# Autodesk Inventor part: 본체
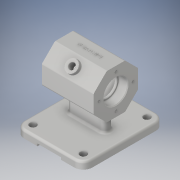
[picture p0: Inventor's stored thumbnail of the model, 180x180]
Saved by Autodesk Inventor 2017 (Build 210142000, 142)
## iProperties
Part Number: 본체
Material: 알루미늄 6061
Document SubType Name: Modeling
Designer: Administrator
Density: 2.7 g/cm^3
Appearance: 알루미늄 - 평지
Mass: 559.154 g
Surface Area: 567.652 cm^2
Volume: 207.094 cm^3
Author: Administrator
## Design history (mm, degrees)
sketch "스케치1"
  geometry: L1 (46, 55)-(-46, 55); L2 (-46, 55)-(-46, -55); L3 (-46, -55)-(46, -55); L4 (46, -55)-(46, 55); L5 (46, 55)-(-46, -55); L6 (-46, 55)-(46, -55); 1 further point
  constraints: 12 end point, 2 midpoint, 2 parallel, 1 horizontal, 1 perpendicular
  dimensions: "d0" = 92 distance of L2.end L3.end; "d1" = 110 distance of L1.end L2.end
extrude "돌출1" new body sketch "스케치1" distance "d2" = 10; taper "d3" = 0 deg
sketch "스케치2"
  geometry: L1 (92, 12.426)-(92, -12.426); L2 (92, -12.426)-(74.426, -30); L3 (74.426, -30)-(49.574, -30); L4 (49.574, -30)-(32, -12.426); L5 (32, -12.426)-(32, 12.426); L6 (32, 12.426)-(49.574, 30); L7 (49.574, 30)-(74.426, 30); L8 (74.426, 30)-(92, 12.426); C1 r 30 at (62, 0); 2 further points
  constraints: 16 end point, 1 centre point, 1 coincident, 1 horizontal alignment, 17 other
  dimensions: "d6" = 60 distance between parallel lines of L6 L2; "d7" = 60 diameter of C1; "d8" = 62 distance of point (62, 0) point (0, 0); "d10" = 92 distance from line of point (0, 0) L1
extrude "돌출2" join sketch "스케치2" stored distance "d11" = 70; taper "d12" = 0 deg
sketch "스케치3"
  geometry: L1 (-20, 0)-(20, 0); L2 (-20, -6)-(20, -6); L3 (20, 6)-(-20, 6); A1 r 6 centre (-20, 0) between (-20, 6) and (-20, -6); A2 r 6 centre (20, 0) between (20, -6) and (20, 6); 2 further points
  constraints: 8 end point, 4 point on circle, 4 tangent, 2 centre point, 2 coincident, 1 horizontal, 1 midpoint, 1 parallel
  dimensions: "d13" = 12 distance between parallel lines of L2 L3; "d14" = 40 distance of L1.end L1.start
extrude "돌출3" join sketch "스케치3" distance "d15" = 70; taper "d16" = 0 deg
sketch "스케치4"
  geometry: L1 (30, 0)-(62, 0); L2 (62, 0)-(62, 3); L3 (62, 3)-(30, 3); L4 (30, 3)-(30, 0); L5 (0, 0)-(92, 0) reference; 5 further points
  constraints: 8 end point, 4 midpoint, 2 parallel, 1 coincident, 1 horizontal, 1 perpendicular, 1 vertical alignment
  dimensions: "d17" = 32 distance of L2.end L3.end; "d18" = 3 distance of L1.end L2.end
extrude "돌출4" cut sketch "스케치4" stored distance "d19" = 70; taper "d20" = 0 deg
fillet "모깎기1" dims "d21" = 12
sketch "스케치5"
  geometry: A1 r 12 centre (-34, 43) between (-34, 55) and (-46, 43) reference; A2 r 12 centre (34, 43) between (46, 43) and (34, 55) reference; A3 r 12 centre (34, -43) between (34, -55) and (46, -43) reference; A4 r 12 centre (-34, -43) between (-46, -43) and (-34, -55) reference; 5 further points
  constraints: 4 coincident
hole "구멍1" sketch "스케치5" at (-34, 43), (34, 43), (34, -43), (-34, -43) diameter "d22" = 9; stored, may be unused: countersink angle "d26" = 90 deg, drill point angle "d28" = 118 deg; dims "d23" = 6, "d24" = 4, "d25" = 2, "d27" = 15
sketch "스케치6"
  geometry: L1 (49.574, -30)-(74.426, -30) reference; L2 (62, -30)-(62, 30); L3 (74.426, 30)-(49.574, 30) reference; L4 (74.426, -30)-(92, -12.426) reference; L5 (62, 0)-(86.749, 24.749); L6 (86.749, 24.749)-(92.406, 19.092); L7 (92.406, 19.092)-(67.657, -5.657); L8 (67.657, -5.657)-(62, 0); L9 (92, 12.426)-(74.426, 30) reference; 2 further points
  constraints: 10 end point, 4 midpoint, 2 parallel, 1 perpendicular, 1 point on line
  dimensions: "d35" = 5 distance between parallel lines of L9 L6; "d36" = 16 diameter of L7 L5
revolve "회전1" sketch "스케치6" stored, may be unused: angle "d37" = 90 deg
sketch "스케치7"
  geometry: L1 (-35, 74.426)-(-35, 49.574) reference; L2 (35, 49.574)-(35, 74.426) reference; L3 (-35, 62)-(35, 62); L4 (-35, 62)-(-35, 78); L5 (-35, 92)-(-35, 74.426) reference; L6 (-35, 78)-(-23, 78); L7 (-23, 78)-(-23, 76); L8 (-23, 76)-(-20, 76); L9 (-20, 76)-(-20, 87); L10 (-20, 87)-(20, 87); L11 (20, 87)-(20, 76); L12 (20, 76)-(23, 76); L13 (23, 76)-(23, 78); L14 (23, 78)-(35, 78); L15 (35, 78)-(35, 62); L16 (35, 74.426)-(-35, 74.426) reference; 1 further point
  constraints: 24 end point, 7 perpendicular, 5 point on line, 2 midpoint, 1 horizontal
  dimensions: "d38" = 32 diameter of L6 L3; "d39" = 50 diameter of L10 L3; "d40" = 28 diameter of L8 L3; "d41" = 12 distance of L4.end L6.end; "d42" = 40 distance of L9.end L10.end; "d43" = 12 distance of L13.end L14.end; "d44" = 3 distance of L7.end L8.end
revolve "회전2" sketch "스케치7" stored, may be unused: angle "d45" = 90 deg
sketch "스케치8"
  geometry: C1 r 14 at (0, 62) reference; A1 r 23 centre (0, 62) between (0, 85) and (-23, 62); 3 further points
  constraints: 4 point on circle, 2 horizontal alignment, 2 vertical alignment, 1 centre point, 1 coincident
  dimensions: "d46" = 46 diameter of A1
hole "구멍2" sketch "스케치8" at (0, 85), (-23, 62), (23, 62), (0, 39) diameter "d47" = 3.242; stored, may be unused: countersink angle "d51" = 90 deg, drill point angle "d53" = 118 deg; dims "d48" = 8, "d49" = 4, "d50" = 2, "d52" = 10
node "작업 평면1"
fillet "모깎기2" dims "d54" = 0.3
chamfer "모따기1" distance "d55" = 1; stored, may be unused: second distance "d56" = 2, angle "d57" = 45 deg
fillet "모깎기3" dims "d58" = 3
fillet "모깎기4" dims "d59" = 3
sketch "스케치9"
  geometry: C1 r 8 at (0, 0) reference; 2 further points
  constraints: 1 coincident
hole "구멍3" sketch "스케치9" at (0, 0) diameter "d60" = 8; stored, may be unused: countersink angle "d64" = 90 deg, drill point angle "d66" = 118 deg; dims "d61" = 8, "d62" = 4, "d63" = 2, "d65" = 15
fillet "모깎기5" dims "d67" = 1
fillet "모깎기6" dims "d68" = 1
fillet "모깎기7" dims "d69" = 3
node "작업 평면2"
sketch "스케치10"
  geometry: L1 (0, 0)-(70, 0) reference; L2 (70, 18.816)-(0, 18.816) reference; L3 (0, 2.121)-(0, 17.938) reference; 2 further points
  constraints: 1 other
  dimensions: "d72" = 30 distance from line of point (35, -11.184) L2; "d73" = 35 distance from line of point (35, -11.184) L3
feature "엠보싱1" sketch "스케치10" dims "d0" = 92, "d1" = 110, "d74" = 0.5, "d75" = 0
fillet "모깎기8" dims "d76" = 3
node "솔리드1"
mirror "미러1"
other parameters: "d70" = 22
